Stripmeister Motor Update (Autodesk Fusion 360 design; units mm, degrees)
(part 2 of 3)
sketch "Sketch4" plane through (0, 0, 0) normal (0, 1, 0) x axis (1, 0, 0)
  line L1 (15.875, -65.6907) -> (15.875, -73.6282)
  line L2 (-15.875, -73.6282) -> (-15.875, -65.6907)
  line L3 (15.875, -73.6282) -> (-15.875, -73.6282)
  line L4 (15.875, -65.6907) -> (15.875, -73.6282)
  line L5 (-15.875, -65.6907) -> (15.875, -65.6907)
  line L6 (-15.875, -73.6282) -> (-15.875, -65.6907)
  line L7 (0, -73.6282) -> (0, -65.6907)
  line L8 (-5.2705, -61.7093) -> (5.2705, -61.7093)
  line L9 (-5.2705, -77.6097) -> (-5.2705, -61.7093)
  line L10 (5.2705, -77.6097) -> (-5.2705, -77.6097)
  line L11 (5.2705, -61.7093) -> (5.2705, -77.6097)
  line L12 (-5.2705, -77.6097) -> (5.2705, -61.7093)
  line L13 (5.2705, -77.6097) -> (-5.2705, -61.7093)
  line L14 (5.2705, -69.6595) -> (-5.2705, -69.6595)
  line L15 (-1.0033, -54.102) -> (1.0033, -54.102)
  line L16 (-1.0033, -85.217) -> (-1.0033, -54.102)
  line L17 (1.0033, -85.217) -> (-1.0033, -85.217)
  line L18 (1.0033, -54.102) -> (1.0033, -85.217)
  line L19 (-1.0033, -85.217) -> (1.0033, -54.102)
  line L20 (1.0033, -85.217) -> (-1.0033, -54.102)
  line L21 (1.0033, -82.3595) -> (0, -85.217)
  line L22 (-1.0033, -82.3595) -> (0, -85.217)
  point P3 (15.875, -65.6907)
  point P8 (15.875, -65.6907)
  point P5 (-15.875, -73.6282)
  point P6 (-15.875, -73.6282)
  point P10 (0, -65.6907)
  point P11 (0, -73.6282)
  point P16 (0, -69.6595)
  point P17 (-5.2705, -69.6595)
  point P18 (5.2705, -69.6595)
  point P23 (0, -69.6595)
  point P24 (0, -85.217)
  point P25 (1.0033, -82.3595)
  point P26 (0, -85.217)
  point P27 (-1.0033, -82.3595)
  point P14 (-5.2705, -77.6097)
  point P15 (5.2705, -77.6097)
  point P21 (-1.0033, -85.217)
  point P22 (1.0033, -85.217)
  point P20 (-1.0033, -54.102)
  horizontal L3
  vertical L4
  horizontal L5
  vertical L6
  coincident P3 P8
  coincident P5 P6
  midpoint L5 P10
  midpoint L3 P11
  horizontal L8
  perpendicular L8 L9
  parallel L8 L10
  parallel L9 L11
  coincident L12 P16
  coincident L13 P16
  midpoint L7 P16
  midpoint L9 P17
  midpoint L11 P18
  horizontal L15
  perpendicular L15 L16
  parallel L15 L17
  parallel L16 L18
  coincident L19 P23
  coincident L20 P23
  coincident P16 P23
  midpoint L17 P24
  coincident L18 P25
  symmetric L7 P24 P26
  symmetric L7 P25 P27
  dimension "d185" distance P14 P15 = 10.541
  dimension "d186" distance L8 L10 = 15.9004
  dimension "d187" distance P21 P22 = 2.0066
  dimension "d188" distance P20 P21 = 31.115
  dimension "d189" distance L14 P25 = 12.7
revolve "Revolve1" sketch "Sketch4" AlongAngle 360 bodies "Cutter Wheel"
work_plane "WorkPlane1" AlongDistance -6.35
sketch "Sketch5" plane through (-0.0003, -0.3714, 156.21) normal (0, 0, 1) x axis (1, 0, 0)
  circle C1 centre (0, 0) radius 14.1224
  circle C2 centre (0, 0) radius 6.35
  circle C3 centre (0, 0) radius 25.4
  point P1 (0, 0)
  point P2 (0, 0)
  point P4 (0, 0)
  coincident P1 P2
  concentric C1 C2
  coincident P1 P4
  dimension "d192" diameter C1 = 28.2448
  dimension "d193" diameter C2 = 12.7
  dimension "d194" diameter C3 = 50.8
extrude "Extrude9" new body sketch "Sketch5" profile of C1 C2 along normal blind 34.925
extrude "Extrude10" sketch "Sketch5" profile of C2 to an object
extrude "Extrude11" add sketch "Sketch5" profile of C1 C3 to an object from offset 14.2875 (= "( 9 / 16 ) * 1 in")
sketch "Sketch6" plane through (0, 0, 191.135) normal (0, 0, 1) x axis (-1, 0, 0)
  line L1 (0.0003, 25.7714) -> (0.0003, 0.3714)
  circle C1 centre (0.0003, 0.3714) radius 25.4
  circle C2 centre (0.0003, 19.4214) radius 6.35
  circle C3 centre (-14.8935, 12.2489) radius 6.35
  circle C4 centre (-18.572, -3.8676) radius 6.35
  circle C5 centre (-8.2651, -16.792) radius 6.35
  circle C6 centre (8.2658, -16.792) radius 6.35
  circle C7 centre (18.5727, -3.8676) radius 6.35
  circle C8 centre (14.8942, 12.2489) radius 6.35
  circle C9 centre (11.6309, 24.5225) radius 6.35
  circle C10 centre (26.1339, 6.3362) radius 6.35
  circle C11 centre (20.9578, -16.3416) radius 6.35
  circle C12 centre (0.0003, -26.4342) radius 6.35
  circle C13 centre (-20.9571, -16.3416) radius 6.35
  circle C14 centre (-26.1332, 6.3362) radius 6.35
  circle C15 centre (-11.6302, 24.5225) radius 6.35
  point P2 (0.0003, 0.3714)
  point P3 (0.0003, 0.3714)
  point P4 (0.0003, 25.7714)
  point P5 (0.0003, 19.4214)
  coincident P2 P3
  coincident C1 P4
  vertical L1
  coincident L1 P5
  tangent C1 C2
  tangent C2 C9
  tangent C8 C9
  tangent C2 C15
  tangent C3 C15
  tangent C3 C14
  tangent C4 C14
  tangent C4 C13
  tangent C5 C13
  tangent C5 C12
  tangent C6 C12
  tangent C6 C11
  tangent C7 C11
  tangent C7 C10
  tangent C8 C10
  dimension "d203" diameter C2 = 12.7
  dimension "d207" diameter C9 = 12.7
  dimension "d208" diameter C10 = 12.7
  dimension "d209" diameter C11 = 12.7
  dimension "d210" diameter C12 = 12.7
  dimension "d211" diameter C13 = 12.7
  dimension "d212" diameter C14 = 12.7
  dimension "d213" diameter C15 = 12.7
  dimension "d205" C-Pattern1-Angle = 360
extrude "Extrude12" cut sketch "Sketch6" profile of C1 C2 C3 C4 C5 C6 C7 C8 C9 C10 C11 C12 C13 C14 C15 against normal blind 20.6502
sketch "Sketch7" plane through (0, 0, 0) normal (0, 1, 0) x axis (1, 0, 0)
  line L1 (-21.2442, -170.4975) -> (-14.1227, -170.4975)
  line L2 (-13.2626, -191.135) -> (-21.2442, -191.135)
  line L3 (-22.3533, -170.4975) -> (-21.2442, -170.4975)
  line L4 (-21.2442, -191.135) -> (-22.3533, -191.135)
  line L5 (-24.9227, -170.4975) -> (-22.3533, -170.4975)
  line L6 (-22.3533, -191.135) -> (-24.9227, -191.135)
  line L7 (-5.8156, -191.135) -> (-13.2626, -191.135)
  line L8 (14.1221, -170.4975) -> (21.2435, -170.4975)
  line L9 (21.2435, -191.135) -> (13.2619, -191.135)
  line L10 (13.2619, -191.135) -> (5.8149, -191.135)
  line L11 (5.8149, -191.135) -> (-5.8156, -191.135)
  line L12 (22.3526, -170.4975) -> (24.922, -170.4975)
  line L13 (24.922, -191.135) -> (22.3526, -191.135)
  line L14 (21.2435, -170.4975) -> (22.3526, -170.4975)
  line L15 (22.3526, -191.135) -> (21.2435, -191.135)
  line L16 (14.1221, -156.21) -> (-14.1227, -156.21)
  line L17 (-24.9227, -170.4975) -> (-24.9227, -191.135)
  line L18 (24.922, -170.4975) -> (24.922, -191.135)
  line L19 (-14.1227, -170.4975) -> (-14.1227, -156.21)
  line L20 (14.1221, -170.4975) -> (14.1221, -156.21)
  line L21 (-24.9227, -183.1975) -> (-24.9227, -170.4975)
  line L22 (24.922, -183.1975) -> (24.922, -170.4975)
  line L23 (24.922, -170.4975) -> (-24.9227, -170.4975)
  line L24 (-0.0004, -191.135) -> (-0.0003, -170.4975)
  line L25 (50.7996, -191.135) -> (-0.0004, -191.135)
  line L26 (50.7996, -170.4975) -> (50.7996, -191.135)
  line L27 (-0.0004, -170.4975) -> (50.7996, -170.4975)
  line L28 (-0.0004, -191.135) -> (-0.0004, -170.4975)
  line L29 (35.082, -191.135) -> (24.922, -191.135)
  line L30 (35.082, -183.1975) -> (35.082, -191.135)
  line L31 (24.922, -183.1975) -> (35.082, -183.1975)
  line L32 (24.922, -191.135) -> (24.922, -183.1975)
  arc A1 centre (-0.0003, -148.0403) radius 43.0947 clockwise from (35.082, -173.0679) to (-24.9227, -183.1975)
  point P8 (-24.9227, -170.4975)
  point P22 (-24.9227, -170.4975)
  point P23 (-24.9227, -183.1975)
  point P16 (24.922, -170.4975)
  point P24 (24.922, -170.4975)
  point P27 (24.922, -170.4975)
  point P28 (-0.0003, -170.4975)
  point P29 (-0.0004, -191.135)
  point P19 (24.922, -191.135)
  point P33 (24.922, -191.135)
  point P25 (24.922, -183.1975)
  point P30 (50.7996, -191.135)
  point P34 (35.082, -191.135)
  coincident P8 P22
  coincident L17 P23
  coincident P16 P24
  perpendicular L12 L22
  coincident P16 P27
  midpoint L23 P28
  midpoint L11 P29
  horizontal L25
  vertical L26
  horizontal L27
  vertical L28
  collinear L23 L27
  horizontal L29
  vertical L30
  horizontal L31
  vertical L32
  coincident P19 P33
  coincident A1 P29
  coincident P25 A1
  dimension "d216" distance P22 P23 = 12.7
  dimension "d217" distance P24 P25 = 12.7
  dimension "d219" distance P29 P30 = 50.8
  dimension "d220" distance P33 P34 = 10.16
work_plane "WorkPlane2" RotateAngle 0
work_plane "WorkPlane3" RotateAngle 0
work_plane "WorkPlane4"
sketch "Sketch8" plane through (-0.0003, -0.3714, 160.8667) normal (0, -1, 0) x axis (1, 0, 0)
  line L1 (24.9224, 30.2683) -> (24.9224, 22.3308)
  line L2 (50.8, 30.2683) -> (0, 30.2683)
  line L3 (0, 30.2683) -> (0, 9.6308)
  arc A1 centre (0, -12.8264) radius 43.0947 clockwise from (-24.9224, 22.3308) to (35.0824, 12.2012)
revolve "Revolve3" sketch "Sketch7" AlongAngle 360
delete_face "DeleteFace1"
delete_face "DeleteFace2"
delete_face "DeleteFace3"
delete_face "DeleteFace4"
delete_face "DeleteFace5"
delete_face "DeleteFace6"
delete_face "DeleteFace7"
sketch "Sketch2" plane through (-19.05, 0, 0) normal (1, 0, 0) x axis (0, 1, 0)
  line L1 (-31.75, 15.748) -> (-31.75, 93.472)
  line L2 (-20.574, 93.472) -> (-20.574, 15.748)
  line L3 (-26.162, 26.035) -> (-26.162, 10.16)
  line L4 (-26.162, 85.5663) -> (-26.162, 99.06)
  line L5 (-28.9401, 28.8131) -> (-28.9401, 82.7881)
  line L6 (-23.3839, 82.7881) -> (-23.3839, 28.8131)
  line L7 (-26.162, 26.035) -> (-26.162, 85.5663)
  arc A1 centre (-26.162, 93.472) radius 5.588 clockwise from (-31.75, 93.472) to (-20.574, 93.472)
  arc A2 centre (-26.162, 15.748) radius 5.588 clockwise from (-20.574, 15.748) to (-31.75, 15.748)
  arc A3 centre (-26.162, 28.8131) radius 2.7781 clockwise from (-23.3839, 28.8131) to (-28.9401, 28.8131)
  arc A4 centre (-26.162, 82.7881) radius 2.7781 clockwise from (-28.9401, 82.7881) to (-23.3839, 82.7881)
  point P8 (-26.162, 10.16)
  point P10 (-26.162, 99.06)
  point P11 (-26.162, 85.5663)
  point P9 (-26.162, 26.035)
  midpoint A2 P8
  vertical L3
  midpoint A1 P10
  vertical L4
  tangent L5 A3
  tangent A3 L6
  parallel L5 L6
  tangent L6 A4
  tangent L5 A4
  midpoint P11 A4
  midpoint P9 A3
  dimension "d224" distance P8 P9 = 15.875 (= "( 5 / 8 ) * 1 in")
  dimension "d225" distance P10 P11 = 13.4938 (= "( 17 / 32 ) * 1 in")
  dimension "d226" diameter A3 = 5.5563 (= "( 7 / 32 ) * 1 in")
extrude "Extrude2" cut sketch "Sketch2" profile of L5 A3 L6 A4 against normal blind 9.525
sketch "Sketch3" plane through (0, 0, 127) normal (0, 0, 1) x axis (-1, 0, 0)
  line L1 (19.05, -7.3041) -> (19.05, 7.3041)
  line L2 (15.875, -7.3041) -> (19.05, -7.3041)
  line L3 (15.875, -38.1) -> (15.875, -7.3041)
  line L4 (28.575, -38.1) -> (15.875, -38.1)
  line L5 (28.575, 38.1) -> (28.575, -38.1)
  line L6 (15.875, 38.1) -> (28.575, 38.1)
  line L7 (15.875, 7.3041) -> (15.875, 38.1)
  line L8 (19.05, 7.3041) -> (15.875, 7.3041)
  line L9 (15.875, 36.9341) -> (19.6088, 38.1)
  circle C1 centre (22.225, 25.4) radius 5.5245
  circle C2 centre (22.225, -25.4) radius 5.5245
  point P12 (19.6088, 38.1)
  point P13 (15.875, 36.9341)
  point P7 (28.575, 38.1)
  coincident L6 P12
  coincident L7 P13
  dimension "d229" distance P12 P13 = 3.9116
  dimension "d230" distance P7 P12 = 8.9662
extrude "Extrude3" cut sketch "Sketch3" profile of L6 L7 L9 blind -25.4 from offset -67.6783
sketch "Sketch4" plane through (9.098, -29.136, 0) normal (0.2981, -0.9545, 0) x axis (0.9545, 0.2981, 0)
  line L1 (-30.0738, 59.3217) -> (-26.1622, 59.3217)
  line L2 (-30.0738, 33.9217) -> (-30.0738, 59.3217)
  line L3 (-26.1622, 33.9217) -> (-30.0738, 33.9217)
  line L4 (-26.1622, 59.3217) -> (-26.1622, 33.9217)
  line L5 (-29.1622, 46.9967) -> (-26.1622, 46.9967)
  line L6 (-29.1622, 46.2467) -> (-29.1622, 46.9967)
  line L7 (-26.1622, 46.2467) -> (-29.1622, 46.2467)
  line L8 (-26.1622, 46.9967) -> (-26.1622, 46.2467)
  line L9 (-26.1622, 36.0867) -> (-29.1622, 36.0867)
  line L10 (-29.1622, 36.0867) -> (-29.1622, 36.8367)
  line L11 (-29.1622, 36.8367) -> (-26.1622, 36.8367)
  line L12 (-26.1622, 38.1187) -> (-29.1622, 38.1187)
  line L13 (-29.1622, 38.1187) -> (-29.1622, 38.8687)
  line L14 (-29.1622, 38.8687) -> (-26.1622, 38.8687)
  line L15 (-26.1622, 40.1507) -> (-29.1622, 40.1507)
  line L16 (-29.1622, 40.1507) -> (-29.1622, 40.9007)
  line L17 (-29.1622, 40.9007) -> (-26.1622, 40.9007)
  line L18 (-26.1622, 42.1827) -> (-29.1622, 42.1827)
  line L19 (-29.1622, 42.1827) -> (-29.1622, 42.9327)
  line L20 (-29.1622, 42.9327) -> (-26.1622, 42.9327)
  line L21 (-26.1622, 44.2147) -> (-29.1622, 44.2147)
  line L22 (-29.1622, 44.2147) -> (-29.1622, 44.9647)
  line L23 (-29.1622, 44.9647) -> (-26.1622, 44.9647)
  line L24 (-26.1622, 48.2787) -> (-29.1622, 48.2787)
  line L25 (-29.1622, 48.2787) -> (-29.1622, 49.0287)
  line L26 (-29.1622, 49.0287) -> (-26.1622, 49.0287)
  line L27 (-26.1622, 50.3107) -> (-29.1622, 50.3107)
  line L28 (-29.1622, 50.3107) -> (-29.1622, 51.0607)
  line L29 (-29.1622, 51.0607) -> (-26.1622, 51.0607)
  line L30 (-26.1622, 52.3427) -> (-29.1622, 52.3427)
  line L31 (-29.1622, 52.3427) -> (-29.1622, 53.0927)
  line L32 (-29.1622, 53.0927) -> (-26.1622, 53.0927)
  line L33 (-26.1622, 54.3747) -> (-29.1622, 54.3747)
  line L34 (-29.1622, 54.3747) -> (-29.1622, 55.1247)
  line L35 (-29.1622, 55.1247) -> (-26.1622, 55.1247)
  line L36 (-26.1622, 56.4067) -> (-29.1622, 56.4067)
  line L37 (-29.1622, 56.4067) -> (-29.1622, 57.1567)
  line L38 (-29.1622, 57.1567) -> (-26.1622, 57.1567)
  line L39 (-26.1622, 57.1567) -> (-29.1622, 57.1567)
  line L40 (-29.1622, 57.1567) -> (-27.6622, 57.1567)
  line L41 (-28.4122, 36.0867) -> (-28.4122, 57.1567)
  point P6 (-26.1622, 46.9967)
  point P50 (-27.6622, 57.1567)
  point P51 (-28.4122, 57.1567)
  point P52 (-28.4122, 36.0867)
  point P7 (-29.1622, 46.9967)
  point P9 (-26.1622, 46.2467)
  horizontal L5
  vertical L6
  horizontal L7
  vertical L8
  coincident L4 P6
  midpoint L4 L8
  midpoint L38 P50
  midpoint L40 P51
  coincident L9 P52
  perpendicular L9 L41
  dimension "d234" distance P6 P7 = 3
  dimension "d235" distance P6 P9 = 0.75
  dimension "d238" R-Pattern1-uDistance = 0
  dimension "d239" R-Pattern1-vDistance = 10.16
extrude "Extrude4" cut sketch "Sketch4" profile of L4 L5 L6 L7 L8 L9 L10 L11 L12 L14 L15 L17 L18 L20 L21 L23 L24 L26 L27 L29 L30 L32 L33 L35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 against normal blind 0.25
extrude "Extrude5" cut of existing geometry blind -1.524
sketch "Sketch1" plane through (-15.875, 0, 0) normal (1, 0, 0) x axis (0, 1, 0)
  line L1 (-36.9341, 38.1187) -> (-36.6722, 38.1187)
  line L2 (-36.9341, 36.8367) -> (-36.9341, 38.1187)
  line L3 (-36.6722, 36.8367) -> (-36.9341, 36.8367)
  line L4 (-36.6722, 36.0867) -> (-36.6722, 36.8367)
  line L5 (-36.9341, 36.0867) -> (-36.6722, 36.0867)
  line L6 (-36.9341, 33.9217) -> (-36.9341, 36.0867)
  line L7 (-38.1, 33.9217) -> (-36.9341, 33.9217)
  line L8 (-38.1, 0) -> (-38.1, 33.9217)
  line L9 (38.1, 0) -> (-38.1, 0)
  line L10 (38.1, 127) -> (38.1, 0)
  line L11 (7.3041, 127) -> (38.1, 127)
  line L12 (5.588, 116.84) -> (6.0357, 125.7934)
  line L13 (5.588, 58.2803) -> (5.588, 116.84)
  line L14 (-5.588, 116.84) -> (-5.588, 58.2803)
  line L15 (-6.0357, 125.7934) -> (-5.588, 116.84)
  line L16 (-38.1, 127) -> (-7.3041, 127)
  line L17 (-38.1, 59.3217) -> (-38.1, 127)
  line L18 (-36.9341, 59.3217) -> (-38.1, 59.3217)
  line L19 (-36.9341, 57.1567) -> (-36.9341, 59.3217)
  line L20 (-36.6722, 57.1567) -> (-36.9341, 57.1567)
  line L21 (-36.6722, 56.4067) -> (-36.6722, 57.1567)
  line L22 (-36.9341, 56.4067) -> (-36.6722, 56.4067)
  line L23 (-36.9341, 55.1247) -> (-36.9341, 56.4067)
  line L24 (-36.6722, 55.1247) -> (-36.9341, 55.1247)
  line L25 (-36.6722, 54.3747) -> (-36.6722, 55.1247)
  line L26 (-36.9341, 54.3747) -> (-36.6722, 54.3747)
  line L27 (-36.9341, 53.0927) -> (-36.9341, 54.3747)
  line L28 (-36.6722, 53.0927) -> (-36.9341, 53.0927)
  line L29 (-36.6722, 52.3427) -> (-36.6722, 53.0927)
  line L30 (-36.9341, 52.3427) -> (-36.6722, 52.3427)
  line L31 (-36.9341, 51.0607) -> (-36.9341, 52.3427)
  line L32 (-36.6722, 51.0607) -> (-36.9341, 51.0607)
  line L33 (-36.6722, 50.3107) -> (-36.6722, 51.0607)
  line L34 (-36.9341, 50.3107) -> (-36.6722, 50.3107)
  line L35 (-36.9341, 49.0287) -> (-36.9341, 50.3107)
  line L36 (-36.6722, 49.0287) -> (-36.9341, 49.0287)
  line L37 (-36.6722, 48.2787) -> (-36.6722, 49.0287)
  line L38 (-36.9341, 48.2787) -> (-36.6722, 48.2787)
  line L39 (-36.9341, 46.9967) -> (-36.9341, 48.2787)
  line L40 (-36.6722, 46.9967) -> (-36.9341, 46.9967)
  line L41 (-36.6722, 46.2467) -> (-36.6722, 46.9967)
  line L42 (-36.9341, 46.2467) -> (-36.6722, 46.2467)
  line L43 (-36.9341, 44.9647) -> (-36.9341, 46.2467)
  line L44 (-36.6722, 44.9647) -> (-36.9341, 44.9647)
  line L45 (-36.6722, 44.2147) -> (-36.6722, 44.9647)
  line L46 (-36.9341, 44.2147) -> (-36.6722, 44.2147)
  line L47 (-36.9341, 42.9327) -> (-36.9341, 44.2147)
  line L48 (-36.6722, 42.9327) -> (-36.9341, 42.9327)
  line L49 (-36.6722, 42.1827) -> (-36.6722, 42.9327)
  line L50 (-36.9341, 42.1827) -> (-36.6722, 42.1827)
  line L51 (-36.9341, 40.9007) -> (-36.9341, 42.1827)
  line L52 (-36.6722, 40.9007) -> (-36.9341, 40.9007)
  line L53 (-36.6722, 40.1507) -> (-36.6722, 40.9007)
  line L54 (-36.9341, 40.1507) -> (-36.6722, 40.1507)
  line L55 (-36.9341, 38.8687) -> (-36.9341, 40.1507)
  line L56 (-36.6722, 38.8687) -> (-36.9341, 38.8687)
  line L57 (-36.6722, 38.1187) -> (-36.6722, 38.8687)
  line L58 (-20.574, 15.748) -> (-20.574, 93.472)
  line L59 (-31.75, 93.472) -> (-31.75, 15.748)
  line L60 (-11.475, 89.1) -> (-16.725, 89.1)
  line L61 (-16.725, 88.35) -> (-11.475, 88.35)
  line L62 (-11.475, 97.5667) -> (-16.725, 97.5667)
  line L63 (-16.725, 96.8167) -> (-11.475, 96.8167)
  line L64 (-11.475, 106.0333) -> (-16.725, 106.0333)
  line L65 (-16.725, 105.2833) -> (-11.475, 105.2833)
  line L66 (-16.725, 113.75) -> (-11.475, 113.75)
  line L67 (-11.475, 114.5) -> (-16.725, 114.5)
  line L68 (-11.475, 108.15) -> (-16.725, 108.15)
  line L69 (-16.725, 107.4) -> (-11.475, 107.4)
  line L70 (-11.475, 99.6833) -> (-16.725, 99.6833)
  line L71 (-16.725, 98.9333) -> (-11.475, 98.9333)
  line L72 (-11.475, 91.2167) -> (-16.725, 91.2167)
  line L73 (-16.725, 90.4667) -> (-11.475, 90.4667)
  line L74 (-11.475, 95.45) -> (-16.725, 95.45)
  line L75 (-16.725, 94.7) -> (-11.475, 94.7)
  line L76 (-11.475, 103.9167) -> (-16.725, 103.9167)
  line L77 (-16.725, 103.1667) -> (-11.475, 103.1667)
  line L78 (-11.475, 112.3833) -> (-16.725, 112.3833)
  line L79 (-16.725, 111.6333) -> (-11.475, 111.6333)
  line L80 (-11.475, 110.2667) -> (-16.725, 110.2667)
  line L81 (-16.725, 109.5167) -> (-11.475, 109.5167)
  line L82 (-11.475, 101.8) -> (-16.725, 101.8)
  line L83 (-16.725, 101.05) -> (-11.475, 101.05)
  line L84 (-11.475, 93.3333) -> (-16.725, 93.3333)
  line L85 (-16.725, 92.5833) -> (-11.475, 92.5833)
  line L86 (-28.9401, 82.7881) -> (-28.9401, 28.8131)
  line L87 (-23.3839, 28.8131) -> (-23.3839, 82.7881)
  line L88 (-31.75, 15.748) -> (-31.75, 93.472)
  line L89 (-20.574, 93.472) -> (-20.574, 15.748)
  line L90 (-16.637, 105.41) -> (-35.687, 105.41)
  line L91 (-16.637, 41.91) -> (-16.637, 105.41)
  line L92 (-35.687, 41.91) -> (-16.637, 41.91)
  line L93 (-35.687, 105.41) -> (-35.687, 41.91)
  line L94 (-26.162, 105.41) -> (-26.162, 82.7881)
  line L95 (-26.162, 61.8998) -> (-26.162, 99.06)
  line L96 (-38.1, 93.472) -> (-38.1, 15.748)
  line L97 (-14.224, 15.748) -> (-14.224, 93.472)
  line L98 (-28.9401, 28.8131) -> (-28.9401, 82.7881)
  line L99 (-23.3839, 82.7881) -> (-23.3839, 28.8131)
  line L100 (-38.1, 0) -> (38.1, 0)
  line L101 (-38.1, 127) -> (-38.1, 0)
  line L102 (38.1, 127) -> (-38.1, 127)
  line L103 (38.1, 0) -> (38.1, 127)
  arc A1 centre (7.3041, 125.73) radius 1.27 clockwise from (6.0357, 125.7934) to (7.3041, 127)
  arc A2 centre (0, 58.2803) radius 5.588 clockwise from (5.588, 58.2803) to (-5.588, 58.2803)
  arc A3 centre (-7.3041, 125.73) radius 1.27 clockwise from (-7.3041, 127) to (-6.0357, 125.7934)
  arc A4 centre (-26.162, 15.748) radius 5.588 clockwise from (-20.574, 15.748) to (-31.75, 15.748)
  arc A5 centre (-26.162, 93.472) radius 5.588 clockwise from (-31.75, 93.472) to (-20.574, 93.472)
  circle C1 centre (0, 38.1) radius 11.049
  arc A6 centre (-11.475, 88.725) radius 0.375 clockwise from (-11.475, 89.1) to (-11.475, 88.35)
  arc A7 centre (-16.725, 88.725) radius 0.375 clockwise from (-16.725, 88.35) to (-16.725, 89.1)
  arc A8 centre (-11.475, 97.1917) radius 0.375 clockwise from (-11.475, 97.5667) to (-11.475, 96.8167)
  arc A9 centre (-16.725, 97.1917) radius 0.375 clockwise from (-16.725, 96.8167) to (-16.725, 97.5667)
  arc A10 centre (-11.475, 105.6583) radius 0.375 clockwise from (-11.475, 106.0333) to (-11.475, 105.2833)
  arc A11 centre (-16.725, 105.6583) radius 0.375 clockwise from (-16.725, 105.2833) to (-16.725, 106.0333)
  arc A12 centre (-16.725, 114.125) radius 0.375 clockwise from (-16.725, 113.75) to (-16.725, 114.5)
  arc A13 centre (-11.475, 114.125) radius 0.375 clockwise from (-11.475, 114.5) to (-11.475, 113.75)
  arc A14 centre (-11.475, 107.775) radius 0.375 clockwise from (-11.475, 108.15) to (-11.475, 107.4)
  arc A15 centre (-16.725, 107.775) radius 0.375 clockwise from (-16.725, 107.4) to (-16.725, 108.15)
  arc A16 centre (-11.475, 99.3083) radius 0.375 clockwise from (-11.475, 99.6833) to (-11.475, 98.9333)
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  point P153 (-26.162, 82.7881)
  point P166 (-26.162, 82.7881)
  point P167 (-26.162, 105.41)
  point P162 (-35.687, 105.41)
  point P163 (-16.637, 105.41)
  point P165 (-35.687, 41.91)
  point P168 (-26.162, 99.06)
  point P169 (-26.162, 61.8998)
  horizontal L90
  vertical L91
  horizontal L92
  vertical L93
  coincident P153 P166
  midpoint L90 P167
  parallel L94 L95
  dimension "d245" distance P162 P163 = 19.05
  dimension "d246" distance P162 P165 = 63.5
  dimension "d247" distance P168 P169 = 37.1602
  dimension "d248" = 6.35
  dimension "d475" = -0.25
extrude "Extrude1" new body sketch "Sketch1" along normal blind 31.75
extrude "Extrude2" add sketch "Sketch1" against normal blind 2.794
extrude "Extrude3" of existing geometry blind -2.794
sketch "Sketch2" plane through (15.875, 0, 0) normal (1, 0, 0) x axis (0, 1, 0)
  line L1 (-20.574, 67.4878) -> (-20.574, 93.472)
  line L2 (-31.75, 93.472) -> (-31.75, 67.4878)
  line L3 (-16.637, 41.91) -> (-35.687, 41.91)
  line L4 (-16.637, 88.35) -> (-16.637, 41.91)
  line L5 (-16.725, 88.35) -> (-16.637, 88.35)
  line L6 (-16.637, 89.1) -> (-16.725, 89.1)
  line L7 (-16.637, 92.5833) -> (-16.637, 89.1)
  line L8 (-16.725, 92.5833) -> (-16.637, 92.5833)
  line L9 (-16.637, 93.3333) -> (-16.725, 93.3333)
  line L10 (-16.637, 94.7) -> (-16.637, 93.3333)
  line L11 (-16.725, 94.7) -> (-16.637, 94.7)
  line L12 (-16.637, 95.45) -> (-16.725, 95.45)
  line L13 (-16.637, 96.8167) -> (-16.637, 95.45)
  line L14 (-16.725, 96.8167) -> (-16.637, 96.8167)
  line L15 (-16.637, 97.5667) -> (-16.725, 97.5667)
  line L16 (-16.637, 98.9333) -> (-16.637, 97.5667)
  line L17 (-16.725, 98.9333) -> (-16.637, 98.9333)
  line L18 (-16.637, 99.6833) -> (-16.725, 99.6833)
  line L19 (-16.637, 101.05) -> (-16.637, 99.6833)
  line L20 (-16.725, 101.05) -> (-16.637, 101.05)
  line L21 (-16.637, 101.8) -> (-16.725, 101.8)
  line L22 (-16.637, 103.1667) -> (-16.637, 101.8)
  line L23 (-16.725, 103.1667) -> (-16.637, 103.1667)
  line L24 (-16.637, 103.9167) -> (-16.725, 103.9167)
  line L25 (-16.637, 105.2833) -> (-16.637, 103.9167)
  line L26 (-16.725, 105.2833) -> (-16.637, 105.2833)
  line L27 (-35.687, 105.41) -> (-17.006, 105.41)
  line L28 (-35.687, 41.91) -> (-35.687, 105.41)
  line L29 (-19.177, 41.91) -> (-16.637, 41.91)
  line L30 (-19.177, 105.41) -> (-19.177, 41.91)
  line L31 (-16.637, 105.41) -> (-19.177, 105.41)
  line L32 (-16.637, 41.91) -> (-16.637, 105.41)
  arc A1 centre (-26.162, 67.4878) radius 5.588 clockwise from (-20.574, 67.4878) to (-31.75, 67.4878)
  arc A2 centre (-26.162, 93.472) radius 5.588 clockwise from (-31.75, 93.472) to (-20.574, 93.472)
  arc A3 centre (-16.725, 88.725) radius 0.375 clockwise from (-16.725, 88.35) to (-16.725, 89.1)
  arc A4 centre (-16.725, 92.9583) radius 0.375 clockwise from (-16.725, 92.5833) to (-16.725, 93.3333)
  arc A5 centre (-16.725, 95.075) radius 0.375 clockwise from (-16.725, 94.7) to (-16.725, 95.45)
  arc A6 centre (-16.725, 97.1917) radius 0.375 clockwise from (-16.725, 96.8167) to (-16.725, 97.5667)
  arc A7 centre (-16.725, 99.3083) radius 0.375 clockwise from (-16.725, 98.9333) to (-16.725, 99.6833)
  arc A8 centre (-16.725, 101.425) radius 0.375 clockwise from (-16.725, 101.05) to (-16.725, 101.8)
  arc A9 centre (-16.725, 103.5417) radius 0.375 clockwise from (-16.725, 103.1667) to (-16.725, 103.9167)
  arc A10 centre (-16.725, 105.6583) radius 0.375 clockwise from (-16.725, 105.2833) to (-17.006, 105.41)
  point P53 (-19.177, 105.41)
  point P50 (-16.637, 41.91)
  point P51 (-16.637, 41.91)
  horizontal L29
  vertical L30
  horizontal L31
  vertical L32
  coincident L27 P53
  coincident P50 P51
  dimension "d256" distance L30 L32 = 2.54
extrude "Extrude4" add sketch "Sketch2" profile of L3 L4 L5 A3 L6 L7 L8 A4 L9 L10 L11 A5 L12 L13 L14 A6 L15 L16 L17 A7 L18 L19 L20 A8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 against normal blind 31.75
move "Move1"
sketch "Sketch3" plane through (-18.669, 0, 0) normal (-1, 0, 0) x axis (0, -1, 0)
  line L1 (31.75, 80.772) -> (31.75, 54.7878)
  line L2 (20.574, 54.7878) -> (20.574, 80.772)
  line L3 (26.162, 86.36) -> (26.162, 49.1998)
  arc A1 centre (26.162, 80.772) radius 5.588 clockwise from (20.574, 80.772) to (31.75, 80.772)
  arc A2 centre (26.162, 54.7878) radius 5.588 clockwise from (31.75, 54.7878) to (20.574, 54.7878)
  circle C1 centre (26.162, 67.7799) radius 2.3813
  point P8 (26.162, 49.1998)
  point P9 (26.162, 86.36)
  point P10 (26.162, 67.7799)
  midpoint A2 P8
  midpoint A1 P9
  midpoint L3 P10
  dimension "d259" diameter C1 = 4.7625 (= "( 3 / 16 ) * 1 in")
extrude "Extrude5" cut sketch "Sketch3" profile of C1 against normal blind 12.065
thread "Thread1"
delete_face "DeleteFace1"
sketch "Sketch4" plane through (0, 0, 92.71) normal (0, 0, 1) x axis (-1, 0, 0)
  line L1 (15.875, 35.687) -> (15.875, 16.637)
  line L2 (-15.875, 35.687) -> (15.875, 35.687)
  line L3 (-15.875, 16.637) -> (-15.875, 35.687)
  line L4 (15.875, 16.637) -> (-15.875, 16.637)
  line L5 (-15.875, 16.1282) -> (-15.875, 16.637)
  line L6 (0, 16.129) -> (0, 16.637)
  line L7 (-1.1753, 12.9707) -> (0, 16.129)
  line L8 (-3.175, 12.065) -> (-3.175, 16.637)
  line L9 (15.875, 15.621) -> (15.875, 16.637)
  line L10 (1.1753, 12.9707) -> (0, 16.129)
  arc A1 centre (-15.6591, -8.0645) radius 23.6865 clockwise from (-15.3731, 15.6203) to (-3.3928, 12.1985)
  arc A2 centre (-2.6036, 13.5022) radius 1.524 clockwise from (-1.1753, 12.9707) to (-3.3928, 12.1985)
  arc A3 centre (15.6591, -8.0645) radius 23.6865 clockwise from (3.3928, 12.1985) to (15.875, 15.621)
  arc A4 centre (2.6036, 13.5022) radius 1.524 clockwise from (3.3928, 12.1985) to (1.1753, 12.9707)
  arc A5 centre (-15.367, 16.1282) radius 0.508 clockwise from (-15.3731, 15.6203) to (-15.875, 16.1282)
  arc A6 centre (15.367, 16.1282) radius 0.508 clockwise from (15.875, 16.1282) to (15.3731, 15.6203)
  point P5 (-15.875, 16.637)
  point P6 (-15.875, 16.637)
  point P8 (0, 16.637)
  point P10 (-3.175, 16.637)
  point P11 (-3.175, 12.065)
  point P16 (15.875, 16.637)
  point P7 (-15.875, 15.621)
  point P17 (15.875, 15.621)
  point P9 (0, 16.129)
  point P22 (0, 16.129)
  point P13 (-1.1753, 12.9707)
  point P21 (1.1753, 12.9707)
  point P14 (-3.3928, 12.1985)
  point P19 (3.3928, 12.1985)
  point P23 (-15.875, 16.1282)
  point P27 (15.875, 16.1282)
  point P24 (-15.3731, 15.6203)
  point P28 (15.3731, 15.6203)
  coincident P5 P6
  perpendicular L4 L5
  midpoint L4 P8
  perpendicular L4 L6
  coincident L4 P10
  perpendicular L4 L8
  coincident P11 A1
  tangent A1 A2
  tangent L7 A2
  symmetric P6 L6 P16
  symmetric P7 L6 P17
  symmetric P9 L6 P22
  symmetric L6 A1 A3
  symmetric L6 P13 P21
  symmetric L6 P14 P19
  symmetric L6 A2 A4
  coincident P7 L5
  tangent L5 A5
  tangent A1 A5
  symmetric L6 P23 P27
  symmetric L6 P24 P28
  symmetric L6 A5 A6
  dimension "d262" distance P6 P7 = 1.016
  dimension "d263" distance P8 P9 = 0.508
  dimension "d265" distance P10 P11 = 4.572
  dimension "d266" distance P6 L8 = 12.7
  dimension "d268" radius A2 = 1.524
  dimension "d269" distance P9 P13 = 3.1583
  dimension "d270" radius A1 = 23.6865
  dimension "d271" radius A5 = 0.508
extrude "Extrude6" sketch "Sketch4" profile of L4 L5 L6 L7 A1 A2 L9 A3 A4 L10 A5 A6 blind 39.37
fillet "Fillet1" radius 0.254
sketch "Sketch5" plane through (0, 0, 29.21) normal (0, 0, -1) x axis (1, 0, 0)
  line L1 (15.875, 35.687) -> (15.875, 16.1282)
  line L2 (-15.875, 35.687) -> (15.875, 35.687)
  line L3 (-15.875, 16.1282) -> (-15.875, 35.687)
  line L4 (-0.2381, 15.4893) -> (-1.1753, 12.9707)
  line L5 (1.1753, 12.9707) -> (0.2381, 15.4893)
  line L6 (3.81, 35.687) -> (-3.81, 35.687)
  line L7 (3.81, 11.6459) -> (3.81, 35.687)
  line L8 (-3.81, 11.6459) -> (3.81, 11.6459)
  line L9 (-3.81, 35.687) -> (-3.81, 11.6459)
  arc A1 centre (-15.367, 16.1282) radius 0.508 clockwise from (-15.3731, 15.6203) to (-15.875, 16.1282)
  arc A2 centre (-15.6591, -8.0645) radius 23.6865 clockwise from (-15.3731, 15.6203) to (-3.3928, 12.1985)
  arc A3 centre (-2.6036, 13.5022) radius 1.524 clockwise from (-1.1753, 12.9707) to (-3.3928, 12.1985)
  arc A4 centre (0, 15.4007) radius 0.254 clockwise from (-0.2381, 15.4893) to (0.2381, 15.4893)
  arc A5 centre (2.6036, 13.5022) radius 1.524 clockwise from (3.3928, 12.1985) to (1.1753, 12.9707)
  arc A6 centre (15.6591, -8.0645) radius 23.6865 clockwise from (3.3928, 12.1985) to (15.3731, 15.6203)
  arc A7 centre (15.367, 16.1282) radius 0.508 clockwise from (15.875, 16.1282) to (15.3731, 15.6203)
  point P21 (-3.81, 35.687)
  point P22 (3.81, 35.687)
  point P24 (-3.81, 11.6459)
  horizontal L6
  vertical L7
  horizontal L8
  vertical L9
  coincident L2 P21
  midpoint L2 L6
  dimension "d277" distance P21 P22 = 7.62
  dimension "d278" distance P21 P24 = 24.0411
sketch "Sketch6" plane through (0, -35.687, 0) normal (0, -1, 0) x axis (1, 0, 0)
  line L1 (-15.875, 29.21) -> (-15.875, 92.71)
  line L2 (15.875, 29.21) -> (-15.875, 29.21)
  line L3 (15.875, 92.71) -> (15.875, 29.21)
  line L4 (-15.875, 92.71) -> (15.875, 92.71)
  line L5 (0, 29.21) -> (0, 92.71)
  line L6 (15.875, 31.1404) -> (-15.875, 31.1404)
  line L7 (15.875, 39.37) -> (-15.875, 39.37)
  line L8 (15.875, 51.816) -> (-15.875, 51.816)
  line L9 (-15.875, 29.21) -> (15.875, 29.21)
  line L10 (15.875, 88.773) -> (-15.875, 88.773)
  line L11 (-6.223, 51.816) -> (-6.223, 88.773)
  line L12 (3.5306, 51.816) -> (3.5306, 88.3968)
  line L13 (3.5306, 64.4652) -> (-6.223, 64.4652)
  line L14 (-3.2757, 53.8613) -> (-5.8792, 59.3604)
  line L15 (3.1868, 56.9208) -> (0.5833, 62.4199)
  circle C1 centre (0, 78.3527) radius 10.4204
  circle C2 centre (0, 44.3421) radius 4.9721
  circle C3 centre (0, 34.4424) radius 3.302
  circle C4 centre (-0.0444, 55.3911) radius 3.575
  circle C5 centre (-2.6479, 60.8902) radius 3.575
  point P6 (0, 92.71)
  point P7 (0, 29.21)
  point P8 (0, 78.3527)
  point P9 (0, 44.3421)
  point P10 (0, 34.4424)
  point P11 (-15.875, 31.1404)
  point P12 (15.875, 31.1404)
  point P13 (-15.875, 39.37)
  point P14 (15.875, 39.37)
  point P15 (-15.875, 51.816)
  point P16 (15.875, 51.816)
  point P19 (-15.875, 88.773)
  point P20 (15.875, 88.773)
  point P23 (-6.223, 88.773)
  point P24 (-6.223, 51.816)
  point P26 (3.5306, 51.816)
  point P27 (-6.223, 64.4652)
  point P28 (3.5306, 64.4652)
  point P29 (-3.2757, 53.8613)
  point P30 (0.5833, 62.4199)
  point P31 (3.1868, 56.9208)
  point P32 (-5.8792, 59.3604)
  midpoint L4 P6
  midpoint L2 P7
  coincident L5 P8
  coincident L5 P9
  coincident L5 P10
  coincident L1 P11
  coincident L3 P12
  perpendicular L3 L6
  coincident L1 P13
  coincident L3 P14
  perpendicular L3 L7
  coincident L1 P15
  coincident L3 P16
  perpendicular L3 L8
  coincident L1 P19
  coincident L3 P20
  perpendicular L3 L10
  tangent C1 L10
  tangent C3 L6
  tangent C2 L7
  tangent L8 C4
  coincident L10 P23
  coincident L8 P24
  perpendicular L8 L11
  coincident L8 P26
  perpendicular L8 L12
  tangent C4 L12
  tangent C5 L11
  coincident L11 P27
  coincident L12 P28
  perpendicular L12 L13
  tangent C5 L13
  tangent C5 L15
  tangent C4 L15
  tangent C4 L14
  tangent C5 L14
  coincident C4 P29
  coincident C5 P30
  coincident C4 P31
  coincident C5 P32
  dimension "d279" diameter C1 = 20.8407
  dimension "d280" diameter C2 = 9.9441
  dimension "d281" diameter C3 = 6.604
  dimension "d282" distance L6 L9 = 1.9304
  dimension "d283" distance L7 L9 = 10.16
  dimension "d284" distance L8 L9 = 22.606
  dimension "d285" distance L4 L10 = 3.937
  dimension "d286" diameter C4 = 7.1501
  dimension "d287" diameter C5 = 7.1501
  dimension "d289" distance P19 L11 = 9.652
  dimension "d290" distance L3 L12 = 12.3444
  dimension "d291" distance L4 L13 = 28.2448
extrude "Extrude7" cut sketch "Sketch6" profile of C1 C2 C3 C4 C5 L14 L15 against normal blind 27.94
base_feature "Base Feature1"
base_feature "Base Feature1"
remove_body "RemoveBody1"
remove_body "RemoveBody2"
remove_body "RemoveBody3"
copy_paste_bodies "CopyPasteBodies1"
move "Move1"
align "Align1"
position "Position6"
extrude "Extrude1" add of existing geometry blind 6.35
split "Split1"
remove_instance "RemoveInstance1"
position "Position7"
sketch "Sketch2" plane through (-15.875, 0, 0) normal (1, 0, 0) x axis (0, 1, 0)
  circle C1 centre (0, 38.1) radius 6.8407
  circle C2 centre (0, 38.1) radius 4.35
  circle C3 centre (0, 38.1) radius 4
  circle C4 centre (0, 38.1) radius 4
  circle C5 centre (0, 38.1) radius 7.8423
  circle C6 centre (0, 38.1) radius 14.3129
  concentric C3 C5
  concentric C3 C6
  dimension "d296" diameter C5 = 15.6845
  dimension "d297" diameter C6 = 28.6258
extrude "Extrude2" new body sketch "Sketch2" along normal blind 15.875 (= "( 1.25 / 2 ) * 1 in")
extrude "Extrude3" cut sketch "Sketch2" profile of C5 C6 along normal blind 0.6604
fillet "Fillet1" radius 12.7
work_plane "WorkPlane1" AlongDistance -16.51
sketch "Sketch3" plane through (1.2954, 0, 38.1) normal (-1, 0, 0) x axis (0, 1, 0)
  line L1 (0, -14.3129) -> (0, 0)
  circle C1 centre (0, 0) radius 14.3129
  circle C2 centre (0, 0) radius 4
  arc A1 centre (23.112, -10.5355) radius 25.4 clockwise from (-2.0269, -14.1687) to (0, 0)
  arc A2 centre (24.371, -7.1565) radius 25.4 clockwise from (0, -14.3129) to (0, 0)
  arc A3 centre (0, 0) radius 14.3129 clockwise from (0, -14.3129) to (-2.0269, -14.1687)
  arc A4 centre (25.0512, -4.1947) radius 25.4 clockwise from (1.7093, -14.2105) to (0, 0)
  arc A5 centre (25.3928, -0.6049) radius 25.4 clockwise from (3.7045, -13.8252) to (0, 0)
  arc A6 centre (0, 0) radius 14.3129 clockwise from (3.7045, -13.8252) to (1.7093, -14.2105)
  arc A7 centre (25.2833, 2.4319) radius 25.4 clockwise from (5.329, -13.2839) to (0, 0)
  arc A8 centre (24.6841, 5.9878) radius 25.4 clockwise from (7.1565, -12.3953) to (0, 0)
  arc A9 centre (0, 0) radius 14.3129 clockwise from (7.1565, -12.3953) to (5.329, -13.2839)
  arc A10 centre (23.7924, 8.8929) radius 25.4 clockwise from (8.5855, -11.452) to (0, 0)
  arc A11 centre (22.2933, 12.1725) radius 25.4 clockwise from (10.1207, -10.1207) to (0, 0)
  arc A12 centre (0, 0) radius 14.3129 clockwise from (10.1207, -10.1207) to (8.5855, -11.452)
  arc A13 centre (20.68, 14.7478) radius 25.4 clockwise from (11.257, -8.8397) to (0, 0)
  arc A14 centre (18.3832, 17.5277) radius 25.4 clockwise from (12.3953, -7.1564) to (0, 0)
  arc A15 centre (0, 0) radius 14.3129 clockwise from (12.3953, -7.1564) to (11.257, -8.8397)
  arc A16 centre (16.1584, 19.5976) radius 25.4 clockwise from (13.1613, -5.6249) to (0, 0)
  arc A17 centre (13.2203, 21.6883) radius 25.4 clockwise from (13.8252, -3.7045) to (0, 0)
  arc A18 centre (0, 0) radius 14.3129 clockwise from (13.8252, -3.7045) to (13.1613, -5.6249)
  arc A19 centre (10.5355, 23.112) radius 25.4 clockwise from (14.1687, -2.0269) to (0, 0)
  arc A20 centre (7.1565, 24.371) radius 25.4 clockwise from (14.3129, 0) to (0, 0)
  arc A21 centre (0, 0) radius 14.3129 clockwise from (14.3129, 0) to (14.1687, -2.0269)
  arc A22 centre (4.1947, 25.0512) radius 25.4 clockwise from (14.2105, 1.7093) to (0, 0)
  arc A23 centre (0.6049, 25.3928) radius 25.4 clockwise from (13.8252, 3.7045) to (0, 0)
  arc A24 centre (0, 0) radius 14.3129 clockwise from (13.8252, 3.7045) to (14.2105, 1.7093)
  arc A25 centre (-2.4319, 25.2833) radius 25.4 clockwise from (13.2839, 5.329) to (0, 0)
  arc A26 centre (-5.9878, 24.6841) radius 25.4 clockwise from (12.3953, 7.1565) to (0, 0)
  arc A27 centre (0, 0) radius 14.3129 clockwise from (12.3953, 7.1565) to (13.2839, 5.329)
  arc A28 centre (-8.8929, 23.7924) radius 25.4 clockwise from (11.452, 8.5855) to (0, 0)
  arc A29 centre (-12.1725, 22.2933) radius 25.4 clockwise from (10.1207, 10.1207) to (0, 0)
  arc A30 centre (0, 0) radius 14.3129 clockwise from (10.1207, 10.1207) to (11.452, 8.5855)
  arc A31 centre (-14.7478, 20.68) radius 25.4 clockwise from (8.8397, 11.257) to (0, 0)
  arc A32 centre (-17.5277, 18.3832) radius 25.4 clockwise from (7.1565, 12.3953) to (0, 0)
  arc A33 centre (0, 0) radius 14.3129 clockwise from (7.1565, 12.3953) to (8.8397, 11.257)
  arc A34 centre (-19.5976, 16.1584) radius 25.4 clockwise from (5.6249, 13.1613) to (0, 0)
  arc A35 centre (-21.6883, 13.2203) radius 25.4 clockwise from (3.7045, 13.8252) to (0, 0)
  arc A36 centre (0, 0) radius 14.3129 clockwise from (3.7045, 13.8252) to (5.6249, 13.1613)
  arc A37 centre (-23.112, 10.5355) radius 25.4 clockwise from (2.0269, 14.1687) to (0, 0)
  arc A38 centre (-24.371, 7.1565) radius 25.4 clockwise from (0, 14.3129) to (0, 0)
  arc A39 centre (0, 0) radius 14.3129 clockwise from (0, 14.3129) to (2.0269, 14.1687)
  arc A40 centre (-25.0512, 4.1947) radius 25.4 clockwise from (-1.7093, 14.2105) to (0, 0)
  arc A41 centre (-25.3928, 0.6049) radius 25.4 clockwise from (-3.7045, 13.8252) to (0, 0)
  arc A42 centre (0, 0) radius 14.3129 clockwise from (-3.7045, 13.8252) to (-1.7093, 14.2105)
  arc A43 centre (-25.2833, -2.4319) radius 25.4 clockwise from (-5.329, 13.2839) to (0, 0)
  arc A44 centre (-24.6841, -5.9878) radius 25.4 clockwise from (-7.1565, 12.3953) to (0, 0)
  arc A45 centre (0, 0) radius 14.3129 clockwise from (-7.1565, 12.3953) to (-5.329, 13.2839)
  arc A46 centre (-23.7924, -8.8929) radius 25.4 clockwise from (-8.5855, 11.452) to (0, 0)
  arc A47 centre (-22.2933, -12.1725) radius 25.4 clockwise from (-10.1207, 10.1207) to (0, 0)
  arc A48 centre (0, 0) radius 14.3129 clockwise from (-10.1207, 10.1207) to (-8.5855, 11.452)
  arc A49 centre (-20.68, -14.7478) radius 25.4 clockwise from (-11.257, 8.8397) to (0, 0)
  arc A50 centre (-18.3832, -17.5277) radius 25.4 clockwise from (-12.3953, 7.1565) to (0, 0)
  arc A51 centre (0, 0) radius 14.3129 clockwise from (-12.3953, 7.1565) to (-11.257, 8.8397)
  arc A52 centre (-16.1584, -19.5976) radius 25.4 clockwise from (-13.1613, 5.6249) to (0, 0)
  arc A53 centre (-13.2203, -21.6883) radius 25.4 clockwise from (-13.8252, 3.7045) to (0, 0)
  arc A54 centre (0, 0) radius 14.3129 clockwise from (-13.8252, 3.7045) to (-13.1613, 5.6249)
  arc A55 centre (-10.5355, -23.112) radius 25.4 clockwise from (-14.1687, 2.0269) to (0, 0)
  arc A56 centre (-7.1565, -24.371) radius 25.4 clockwise from (-14.3129, 0) to (0, 0)
  arc A57 centre (0, 0) radius 14.3129 clockwise from (-14.3129, 0) to (-14.1687, 2.0269)
  arc A58 centre (-4.1947, -25.0512) radius 25.4 clockwise from (-14.2105, -1.7093) to (0, 0)
  arc A59 centre (-0.6049, -25.3928) radius 25.4 clockwise from (-13.8252, -3.7045) to (0, 0)
  arc A60 centre (0, 0) radius 14.3129 clockwise from (-13.8252, -3.7045) to (-14.2105, -1.7093)
  arc A61 centre (2.4319, -25.2833) radius 25.4 clockwise from (-13.2839, -5.329) to (0, 0)
  arc A62 centre (5.9878, -24.6841) radius 25.4 clockwise from (-12.3953, -7.1564) to (0, 0)
  arc A63 centre (0, 0) radius 14.3129 clockwise from (-12.3953, -7.1564) to (-13.2839, -5.329)
  arc A64 centre (8.8929, -23.7924) radius 25.4 clockwise from (-11.452, -8.5855) to (0, 0)
  arc A65 centre (12.1725, -22.2933) radius 25.4 clockwise from (-10.1207, -10.1207) to (0, 0)
  arc A66 centre (0, 0) radius 14.3129 clockwise from (-10.1207, -10.1207) to (-11.452, -8.5855)
  arc A67 centre (14.7478, -20.68) radius 25.4 clockwise from (-8.8397, -11.257) to (0, 0)
  arc A68 centre (17.5277, -18.3832) radius 25.4 clockwise from (-7.1565, -12.3953) to (0, 0)
  arc A69 centre (0, 0) radius 14.3129 clockwise from (-7.1565, -12.3953) to (-8.8397, -11.257)
  arc A70 centre (19.5976, -16.1584) radius 25.4 clockwise from (-5.6249, -13.1613) to (0, 0)
  arc A71 centre (21.6883, -13.2203) radius 25.4 clockwise from (-3.7045, -13.8252) to (0, 0)
  arc A72 centre (0, 0) radius 14.3129 clockwise from (-3.7045, -13.8252) to (-5.6249, -13.1613)
  point P4 (-2.0269, -14.1687)
  point P2 (0, 0)
  point P3 (0, 0)
  point P7 (0, -14.3129)
  point P6 (0, 0)
  point P9 (0, 0)
  point P10 (0, -14.3129)
  coincident C1 P4
  coincident P2 P3
  coincident C1 P7
  coincident P2 P6
  coincident P2 P9
  coincident C1 P10
  vertical L1
  coincident P7 P10
  dimension "d305" distance P4 P7 = 2.032
  dimension "d306" radius A2 = 25.4
  dimension "d307" radius A1 = 25.4
  dimension "d308" radius A3 = 14.3129
  dimension "d310" C-Pattern1-Angle = 360
extrude "Extrude4" add sketch "Sketch3" profile of C2 A1 A2 A3 A4 A5 A6 A7 A8 A9 A10 A11 A12 A13 A14 A15 A16 A17 A18 A19 A20 A21 A22 A23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 along normal blind 16.51
extrude "Extrude5" cut of existing geometry blind -16.51
extrude "Extrude6" cut of existing geometry to an object
sketch "Sketch4" plane through (-15.875, 0, 0) normal (-1, 0, 0) x axis (0, -1, 0)
  circle C1 centre (0, 38.1) radius 7.8423
  circle C2 centre (0, 38.1) radius 4
  circle C3 centre (0, 38.1) radius 14.224
  concentric C1 C3
  dimension "d317" diameter C3 = 28.448
extrude "Extrude7" new body sketch "Sketch4" profile of C1 C3 against normal blind 15.748
delete_face "DeleteFace1"
fillet "Fillet2" radius 13.208
extrude "Extrude8" cut of existing geometry to an object
combine "Combine1"
extrude "Extrude9" new body of existing geometry blind -77.4954
combine "Combine2"
mirror "Mirror1" mirrorStitchTolerance 0.1016
fillet "Fillet3" radius 0.635
fillet "Fillet4" radius 0.254
sketch "Sketch5" plane through (53.6875, 0, 0) normal (1, 0, 0) x axis (0, 1, 0)
  line L1 (2.3812, 41.314) -> (-2.3813, 41.314)
  line L2 (-3.974, 38.5552) -> (-1.5928, 34.4308)
  line L3 (1.5928, 34.4308) -> (3.974, 38.5552)
  circle C1 centre (0, 38.1) radius 4
  point P3 (-2.3813, 41.314)
  point P4 (2.3812, 41.314)
  coincident C1 P3
  coincident C1 P4
  horizontal L1
  dimension "d332" distance P3 P4 = 4.7625 (= "( 3 / 16 ) * 1 in")
  dimension "d334" C-Pattern1-Angle = 360
extrude "Extrude10" cut sketch "Sketch5" against normal blind 25.4
fillet "Fillet5" radius 1.27
base_feature "Base Feature1"
position "Position8"
copy_paste "CutPaste1"
copy_paste "CutPaste2"
copy_paste "CutPaste3"
copy_paste "CutPaste4"
copy_paste "CutPaste1"
sketch "Sketch7" plane through (0, -35.687, 0) normal (0, -1, 0) x axis (1, 0, 0)
  line L1 (-5.8792, 59.3604) -> (-3.2757, 53.8613)
  line L2 (3.1868, 56.9208) -> (0.5833, 62.4199)
  line L3 (-15.875, 29.21) -> (-15.875, 92.71)
  line L4 (15.875, 29.21) -> (-15.875, 29.21)
  line L5 (15.875, 92.71) -> (15.875, 29.21)
  line L6 (-15.875, 92.71) -> (15.875, 92.71)
  line L7 (11.43, 29.21) -> (-11.43, 29.21)
  line L8 (11.43, 41.1163) -> (11.43, 29.21)
  line L9 (15.875, 41.1163) -> (11.43, 41.1163)
  line L10 (0, 34.4424) -> (0, 29.21)
  line L11 (-11.43, 41.1163) -> (-11.43, 29.21)
  line L12 (-15.875, 41.1163) -> (-11.43, 41.1163)
  circle C1 centre (0, 44.3421) radius 4.9721
  circle C2 centre (0, 34.4424) radius 3.302
  arc A1 centre (-0.0444, 55.3911) radius 3.5751 clockwise from (3.1868, 56.9208) to (-3.2757, 53.8613)
  arc A2 centre (-2.6479, 60.8902) radius 3.575 clockwise from (-5.8792, 59.3604) to (0.5833, 62.4199)
  circle C3 centre (0, 78.3527) radius 10.4204
  point P15 (-11.43, 29.21)
  point P18 (15.875, 41.1163)
  point P19 (0, 29.21)
  point P3 (0, 34.4424)
  point P20 (0, 34.4424)
  point P16 (11.43, 29.21)
  point P21 (-11.43, 29.21)
  point P17 (11.43, 41.1163)
  point P22 (-11.43, 41.1163)
  point P23 (-15.875, 41.1163)
  coincident L4 P15
  midpoint L4 L7
  perpendicular L4 L8
  coincident L5 P18
  perpendicular L5 L9
  midpoint L4 P19
  coincident P3 P20
  symmetric P16 L10 P21
  symmetric P17 L10 P22
  symmetric P18 L10 P23
  dimension "d339" distance P15 P16 = 22.86
  dimension "d340" distance P16 P17 = 11.9062 (= "( 15 / 32 ) * 1 in")
extrude "Extrude8" cut sketch "Sketch7" profile of L3 L4 L5 L8 L9 L11 L12 against normal blind 30.48
fillet "Fillet2" radius 2.54
chamfer "Chamfer1" distance 0.254 Rotate Angle 85
base_feature "Base Feature1"
position "Position9"
position "Position10"
sketch "Sketch3" plane through (0, 0, -12.7) normal (0, 0, -1) x axis (1, 0, 0)
  line L1 (30.1625, -74.8109) -> (-30.1625, -74.8109)
  line L2 (38.1, 66.8734) -> (38.1, -66.8734)
  line L3 (-30.1625, 74.8109) -> (30.1625, 74.8109)
  line L4 (-38.1, -66.8734) -> (-38.1, 66.8734)
  line L5 (12.7, 0.6112) -> (12.7, 32.7422)
  line L6 (-7.9375, -4.1513) -> (7.9375, -4.1513)
  line L7 (-12.7, 32.7422) -> (-12.7, 0.6112)
  line L8 (7.9375, 37.5047) -> (-7.9375, 37.5047)
  line L9 (38.1, 0) -> (-38.1, 0)
  line L10 (0, 74.8109) -> (0, 0)
  line L11 (0, 72.9059) -> (0, 74.8109)
  circle C1 centre (22.225, -25.4) radius 5.1594
  circle C2 centre (22.225, 25.4) radius 5.1594
  circle C3 centre (-22.225, -25.4) radius 5.1594
  circle C4 centre (-22.225, 25.4) radius 5.1594
  circle C5 centre (0, -14.8669) radius 5.1594
  arc A1 centre (-30.1625, -66.8734) radius 7.9375 clockwise from (-30.1625, -74.8109) to (-38.1, -66.8734)
  arc A2 centre (30.1625, -66.8734) radius 7.9375 clockwise from (38.1, -66.8734) to (30.1625, -74.8109)
  arc A3 centre (30.1625, 66.8734) radius 7.9375 clockwise from (30.1625, 74.8109) to (38.1, 66.8734)
  arc A4 centre (-30.1625, 66.8734) radius 7.9375 clockwise from (-38.1, 66.8734) to (-30.1625, 74.8109)
  circle C6 centre (28.575, 65.2859) radius 3.9687
  circle C7 centre (-28.575, 65.2859) radius 3.9687
  circle C8 centre (0, -62.4919) radius 3.9687
  arc A5 centre (7.9375, 0.6112) radius 4.7625 clockwise from (12.7, 0.6112) to (7.9375, -4.1513)
  arc A6 centre (-7.9375, 0.6112) radius 4.7625 clockwise from (-7.9375, -4.1513) to (-12.7, 0.6112)
  arc A7 centre (-7.9375, 32.7422) radius 4.7625 clockwise from (-12.7, 32.7422) to (-7.9375, 37.5047)
  arc A8 centre (7.9375, 32.7422) radius 4.7625 clockwise from (7.9375, 37.5047) to (12.7, 32.7422)
  circle C9 centre (30.1625, 66.8734) radius 7.9375
  circle C10 centre (-30.1625, 66.8734) radius 7.9375
  arc A9 centre (0, 304.7074) radius 231.8015 clockwise from (29.1639, 74.7479) to (-29.1639, 74.7479)
  circle C11 centre (30.1625, -66.8734) radius 7.9375
  arc A10 centre (0, -304.7074) radius 231.8015 clockwise from (-29.1639, -74.7479) to (29.1639, -74.7479)
  circle C12 centre (-30.1625, -66.8734) radius 7.9375
  point P36 (-38.1, 0)
  point P37 (38.1, 0)
  point P1 (0, 0)
  point P39 (0, 0)
  point P40 (0, 74.8109)
  point P41 (-29.1639, 74.7479)
  point P42 (29.1639, 74.7479)
  point P43 (0, 72.9059)
  point P46 (-29.1639, -74.7479)
  point P47 (29.1639, -74.7479)
  tangent A3 C9
  tangent A4 C10
  midpoint L4 P36
  midpoint L2 P37
  tangent C9 A9
  tangent C10 A9
  coincident P1 P39
  midpoint L3 P40
  coincident C10 P41
  coincident C9 P42
  perpendicular L3 L11
  coincident A9 P43
  symmetric C9 L9 C11
  symmetric C10 L9 C12
  symmetric L9 A9 A10
  symmetric L9 P41 P46
  symmetric L9 P42 P47
  dimension "d347" diameter C9 = 15.875
  dimension "d348" diameter C10 = 15.875
  dimension "d349" distance P40 P43 = 1.905
work_plane "WorkPlane1" AlongDistance 0
extrude "Extrude6" cut sketch "Sketch3" profile of L1 L3 C9 C10 A9 C11 A10 C12 against normal blind 12.7
sketch "Sketch4" plane through (0, -74.8109, -6.35) normal (0, -1, 0) x axis (1, 0, 0)
  line L1 (29.1639, -6.35) -> (-29.1639, -6.35)
  line L2 (-29.1639, 6.35) -> (29.1639, 6.35)
  line L3 (-29.1639, -6.35) -> (-38.1, -6.35)
  line L4 (38.1, -6.35) -> (29.1639, -6.35)
  line L5 (-38.1, 6.35) -> (-38.1, -6.35)
  line L6 (-38.1, 6.35) -> (-29.1639, 6.35)
  line L7 (38.1, 6.35) -> (29.1639, 6.35)
  line L8 (38.1, -6.35) -> (38.1, 6.35)
  curve K1
  curve K2
  curve K3
  curve K4
  line L9 (0, -6.35) -> (0, 6.35)
  line L10 (-25.4, 3.175) -> (25.4, 3.175)
  line L11 (-25.4, -3.175) -> (-25.4, 3.175)
  line L12 (25.4, -3.175) -> (-25.4, -3.175)
  line L13 (25.4, 3.175) -> (25.4, -3.175)
  line L14 (-25.4, -3.175) -> (25.4, 3.175)
  line L15 (25.4, -3.175) -> (-25.4, 3.175)
  curve K5
  curve K6
  curve K7
  curve K8
  point P10 (0, 6.35)
  point P11 (0, -6.35)
  point P16 (0, 0)
  point P1 (0, 0)
  point P14 (-25.4, -3.175)
  point P15 (25.4, -3.175)
  point P13 (-25.4, 3.175)
  midpoint L2 P10
  midpoint L1 P11
  horizontal L10
  perpendicular L10 L11
  parallel L10 L12
  parallel L11 L13
  coincident L14 P16
  coincident L15 P16
  coincident P1 P16
  collinear K2 L13
  collinear K1 L12
  collinear K3 L10
  coincident K1
  dimension "d356" distance K2 K4 = 50.8
  dimension "d357" distance P14 P15 = 50.8
  dimension "d358" distance P13 P14 = 6.35
  dimension "d355" Text1-Height = 5.588
  dimension "d359" Text2-Height = 2.3813
emboss "Emboss1" sketch "Sketch4" Depth -0.25 Horizontal Distance 0 Vertical Distance 0 Rotation Angle 0
fillet "Fillet3" radius 1.27
fillet "Fillet4" radius 1.27
work_plane "WorkPlane2" AlongDistance -19.05
split "Split1" bodies "Knob (1)"
remove_body "RemoveBody1"
extrude "Extrude13" cut of existing geometry blind -0.254 taper -70
extrude "Extrude14" add of existing geometry blind 0.254
fillet "Fillet5" radius 10.541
